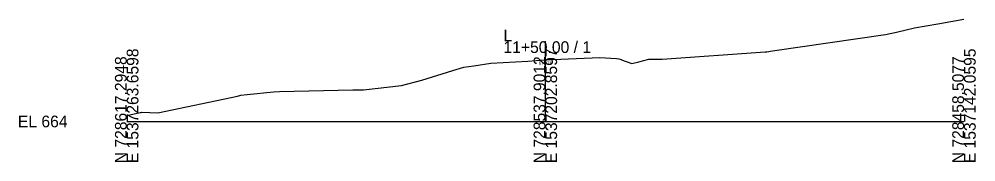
# Model space of a CAD drawing. Extents: x -26 to 1203, y -10 to 9522.
# Drawn here: x -25.7 to 202.8, y 1490.3 to 1524.5 of the extents above; entities that cross this region are included whole.
import ezdxf

# ---------------------------------------------------------------- set-up
doc = ezdxf.new("R2010")
doc.units = 0
for name, color, linetype in [('Default', 7, 'Continuous'), ('Exist Cross Section Cell', 7, 'Continuous'), ('Exist XS Center Line Elevation Label', 7, 'Continuous'), ('Exist XS Ground Line', 7, 'Continuous')]:
    doc.layers.add(name, color=color, linetype=linetype)

msp = doc.modelspace()

# ---------------------------------------------------------------- linework, layer by layer
at = {"layer": 'Exist Cross Section Cell'}
for p, q in [((100, 1500), (100, 1519.21)), ((0, 1500), (100, 1500)), ((100, 1500), (200, 1500))]:
    msp.add_line(p, q, dxfattribs=at)
at = {"layer": 'Exist XS Ground Line'}
msp.add_lwpolyline([(0, 1501.4), (3.23, 1502.13), (3.45, 1502.17), (3.65, 1502.2), (7.41, 1502.03), (26.43, 1506.08), (27.27, 1506.29), (28.79, 1506.47), (35.06, 1507.1), (36.47, 1507.18), (54.04, 1507.54), (54.91, 1507.56), (56.44, 1507.6), (56.56, 1507.6), (65.67, 1508.62), (70.53, 1509.91), (77.91, 1512.25), (80.52, 1513.02), (82.95, 1513.34), (86.97, 1513.94), (95.78, 1514.48), (99.77, 1514.73), (100, 1514.75), (103.72, 1514.92), (113, 1515.34), (117.03, 1515.09), (117.53, 1515.04), (118.13, 1514.82), (118.21, 1514.8), (120.68, 1513.86), (122.3, 1514.28), (124.69, 1514.91), (127.87, 1514.93), (152.55, 1516.69), (152.74, 1516.7), (152.89, 1516.72), (154.24, 1516.93), (181.24, 1520.86), (183.9, 1521.39), (188.21, 1522.4), (193.75, 1523.4), (200, 1524.53)], dxfattribs=at)

# ---------------------------------------------------------------- texts
at = {"layer": 'Default'}
msp.add_text('-', height=0.0001, dxfattribs=at).set_placement((0, 1500))
msp.add_text('-', height=0.0001, dxfattribs=at).set_placement((0, 1500))
msp.add_text('-', height=0.0001, dxfattribs=at).set_placement((0, 1500))
at = {"layer": 'Exist Cross Section Cell'}
for s, p in [('L', (90, 1519.21)), ('11+50.00 / 1', (90, 1516.41)), ('EL 664', (-26, 1498.6))]:
    msp.add_text(s, height=2.8, dxfattribs=at).set_placement(p)
for s, p in [('N 728617.2948', (0, 1490)), ('E 1537263.6598', (2.8, 1490)), ('N 728537.9012', (100, 1490)), ('E 1537202.8597', (102.8, 1490)), ('N 728458.5077', (200, 1490)), ('E 1537142.0595', (202.8, 1490))]:
    msp.add_text(s, height=2.8, rotation=90, dxfattribs=at).set_placement(p)
at = {"layer": 'Exist XS Center Line Elevation Label'}
msp.add_text('678.75', height=0.75, dxfattribs=at).set_placement((98.43, 1513.61))

doc.saveas('drawing.dxf')
